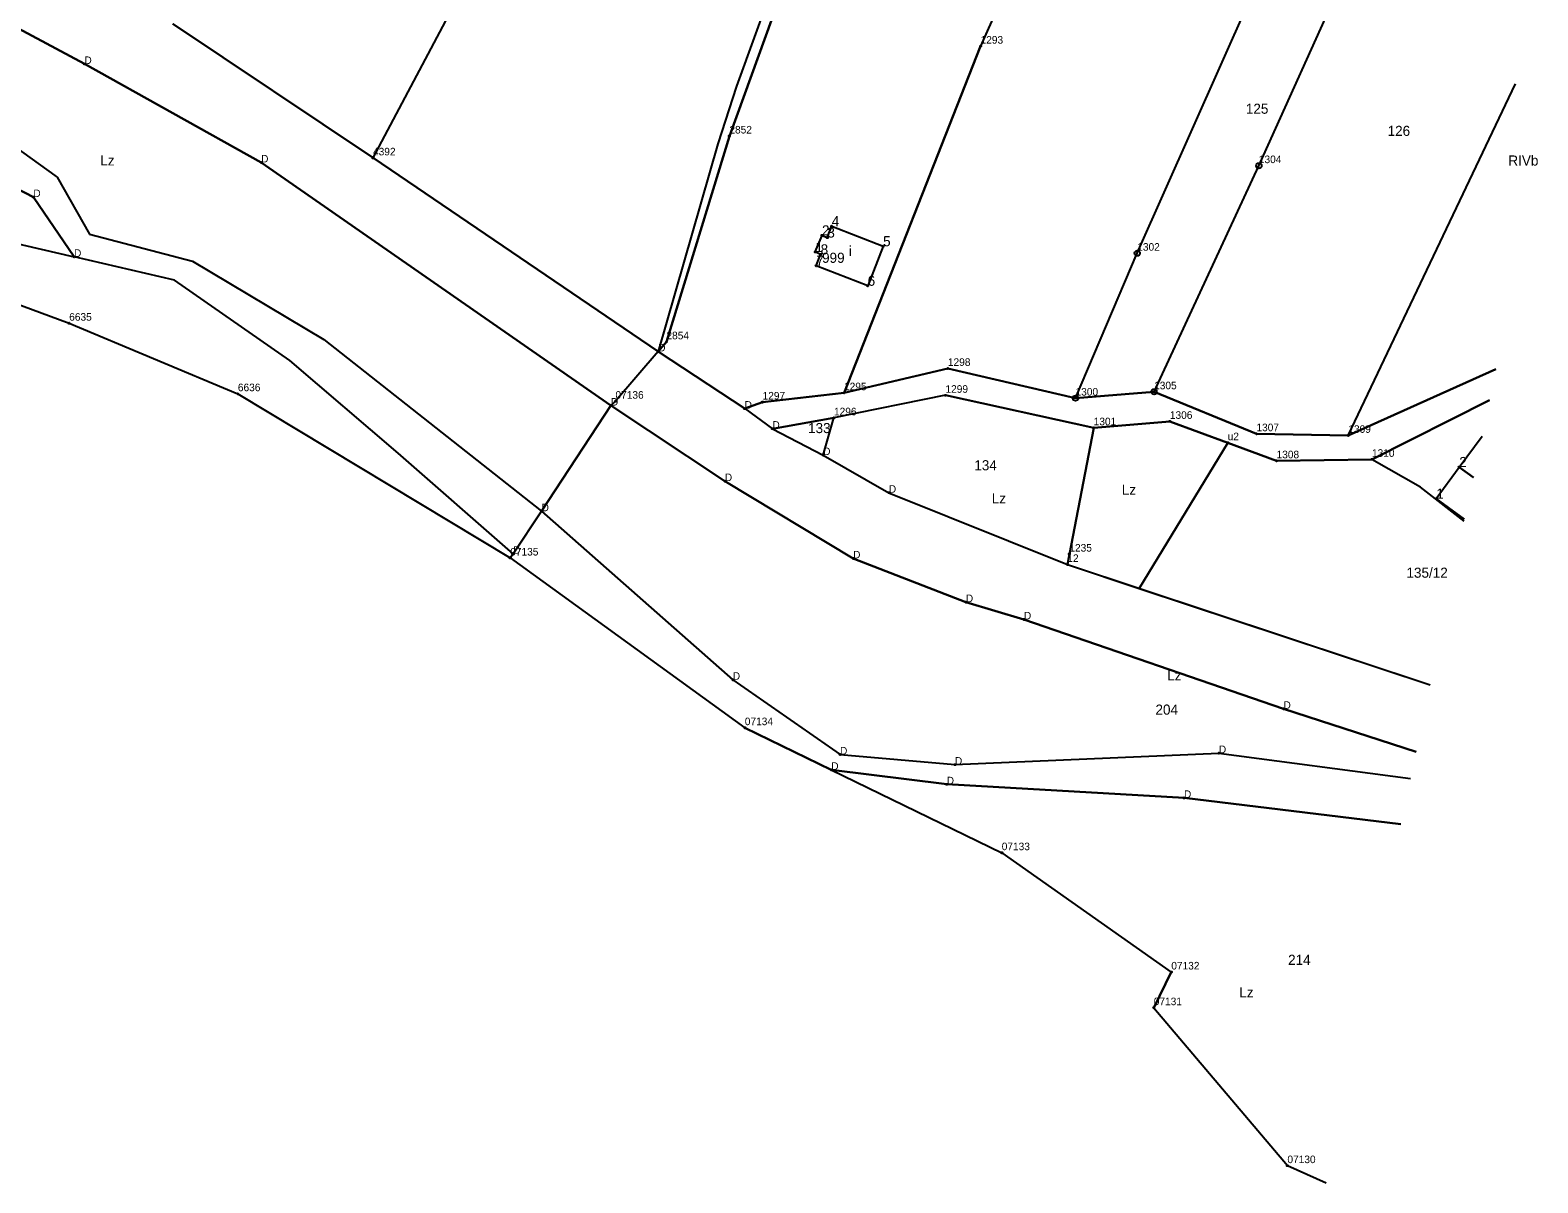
# Model space of a CAD drawing. Extents: x 7465393 to 7466459, y 5491258 to 5492404.
# Drawn here: x 7466235 to 7466458.9, y 5491258.3 to 5491429.5 of the extents above; entities that cross this region are included whole.
import ezdxf

# ---------------------------------------------------------------- set-up
doc = ezdxf.new("R2010")
doc.units = 0
for name, color, linetype in [('202-punkt graniczny', 7, 'Continuous'), ('202-punkt graniczny-Atr103', 7, 'Continuous'), ('203-punkt graniczny', 7, 'Continuous'), ('203-punkt graniczny-Atr103', 7, 'Continuous'), ('209-oznaczenie konturu klasyfikacyjnego', 7, 'Continuous'), ('210-oznaczenie konturu użytku gruntowego', 7, 'Continuous'), ('211-numer działki ewidencyjnej', 7, 'Continuous'), ('217-kontur klasyfikacyjny', 7, 'Continuous'), ('218-kontur użytku gruntowego', 7, 'Continuous'), ('219-działka ewidencyjna', 7, 'Continuous'), ('312-budynek ewidencyjny', 7, 'Continuous'), ('312-oznaczenie budynku ewidencyjnego', 7, 'Continuous'), ('312-oznaczenie budynku ewidencyjnego-Atr117', 7, 'Continuous'), ('Punkt budynku', 7, 'Continuous'), ('Punkt budynku-Atr104', 7, 'Continuous')]:
    doc.layers.add(name, color=color, linetype=linetype)

# ---------------------------------------------------------------- blocks, each defined once
blk = doc.blocks.new('203')
blk.add_circle((0, 0), 0.09)
blk = doc.blocks.new('202')
blk.add_circle((0, 0), 0.4)
blk = doc.blocks.new('PUNKTBUD')
blk.add_circle((0, 0), 0.09)

msp = doc.modelspace()

# ---------------------------------------------------------------- linework, layer by layer
at = {"layer": '217-kontur klasyfikacyjny'}
for points in [[(7466390.84, 5491460.24), (7466376.13, 5491427.07)], [(7466376.13, 5491427.07), (7466355.86, 5491375.61)], [(7466235.52, 5491404.67), (7466207.38, 5491419.24)], [(7466241.56, 5491395.8), (7466235.52, 5491404.67)], [(7466256.45, 5491392.36), (7466241.56, 5491395.8)], [(7466223.97, 5491392.21), (7466240.84, 5491385.94)], [(7466273.58, 5491380.42), (7466256.45, 5491392.36)], [(7466240.84, 5491385.94), (7466265.88, 5491375.47)], [(7466289.66, 5491366.65), (7466273.58, 5491380.42)], [(7466355.86, 5491375.61), (7466371.28, 5491379.23)], [(7466371.28, 5491379.23), (7466390.23, 5491374.82)], [(7466430.72, 5491369.29), (7466452.64, 5491379.14)], [(7466265.88, 5491375.47), (7466306.31, 5491351.09)], [(7466390.23, 5491374.82), (7466401.89, 5491375.77)], [(7466401.89, 5491375.77), (7466417.08, 5491369.53)], [(7466451.68, 5491374.54), (7466434.23, 5491365.73)], [(7466417.08, 5491369.53), (7466430.72, 5491369.29)], [(7466412.81, 5491368.2), (7466399.69, 5491346.58)], [(7466420.07, 5491365.52), (7466412.81, 5491368.2)], [(7466306.73, 5491351.71), (7466289.66, 5491366.65)], [(7466434.23, 5491365.73), (7466420.07, 5491365.52)], [(7466441.44, 5491361.59), (7466434.23, 5491365.73)], [(7466447.93, 5491356.58), (7466441.44, 5491361.59)], [(7466306.31, 5491351.09), (7466306.73, 5491351.71)], [(7466399.69, 5491346.58), (7466442.85, 5491332.26)]]:
    msp.add_lwpolyline(points, dxfattribs=at)
at = {"layer": '218-kontur użytku gruntowego'}
for points in [[(7466243.1, 5491424.43), (7466171.64, 5491462.69)], [(7466390.84, 5491460.24), (7466376.13, 5491427.07)], [(7466345.55, 5491436.73), (7466339.91, 5491421.15)], [(7466346.31, 5491434.42), (7466338.84, 5491413.73)], [(7466256.21, 5491430.41), (7466285.94, 5491410.48)], [(7466211.1, 5491427.7), (7466239.05, 5491407.62)], [(7466376.13, 5491427.07), (7466355.86, 5491375.61)], [(7466269.33, 5491409.81), (7466243.1, 5491424.43)], [(7466339.91, 5491421.15), (7466337.12, 5491412.56)], [(7466235.52, 5491404.67), (7466207.38, 5491419.24)], [(7466337.12, 5491412.56), (7466328.28, 5491381.76)], [(7466338.84, 5491413.73), (7466329.5, 5491383.18)], [(7466321.26, 5491373.72), (7466269.33, 5491409.81)], [(7466285.94, 5491410.48), (7466328.28, 5491381.76)], [(7466239.05, 5491407.62), (7466243.84, 5491399.17)], [(7466241.56, 5491395.8), (7466235.52, 5491404.67)], [(7466243.84, 5491399.17), (7466259.15, 5491395.15)], [(7466256.45, 5491392.36), (7466241.56, 5491395.8)], [(7466259.15, 5491395.15), (7466278.64, 5491383.51)], [(7466273.58, 5491380.42), (7466256.45, 5491392.36)], [(7466278.64, 5491383.51), (7466310.97, 5491358.02)], [(7466329.5, 5491383.18), (7466328.28, 5491381.76)], [(7466328.28, 5491381.76), (7466321.93, 5491374.36)], [(7466328.28, 5491381.76), (7466341.11, 5491373.26)], [(7466289.66, 5491366.65), (7466273.58, 5491380.42)], [(7466371.28, 5491379.23), (7466355.86, 5491375.61)], [(7466390.23, 5491374.82), (7466371.28, 5491379.23)], [(7466452.64, 5491379.14), (7466430.72, 5491369.29)], [(7466321.93, 5491374.36), (7466321.26, 5491373.72)], [(7466343.77, 5491374.24), (7466341.11, 5491373.26)], [(7466355.86, 5491375.61), (7466343.77, 5491374.24)], [(7466370.92, 5491375.24), (7466354.37, 5491371.89)], [(7466392.92, 5491370.42), (7466370.92, 5491375.24)], [(7466401.89, 5491375.77), (7466390.23, 5491374.82)], [(7466417.08, 5491369.53), (7466401.89, 5491375.77)], [(7466434.23, 5491365.73), (7466451.68, 5491374.54)], [(7466321.26, 5491373.72), (7466310.97, 5491358.02)], [(7466338.17, 5491362.5), (7466321.26, 5491373.72)], [(7466341.11, 5491373.26), (7466345.23, 5491370.29)], [(7466354.37, 5491371.89), (7466345.23, 5491370.29)], [(7466345.23, 5491370.29), (7466352.77, 5491366.37)], [(7466392.92, 5491370.42), (7466389.31, 5491351.67)], [(7466404.23, 5491371.37), (7466392.92, 5491370.42)], [(7466412.81, 5491368.2), (7466404.23, 5491371.37)], [(7466430.72, 5491369.29), (7466417.08, 5491369.53)], [(7466399.69, 5491346.58), (7466412.81, 5491368.2)], [(7466412.81, 5491368.2), (7466420.07, 5491365.52)], [(7466306.73, 5491351.71), (7466289.66, 5491366.65)], [(7466352.77, 5491366.37), (7466362.52, 5491360.78)], [(7466420.07, 5491365.52), (7466434.23, 5491365.73)], [(7466441.44, 5491361.59), (7466434.23, 5491365.73)], [(7466357.21, 5491351.03), (7466338.17, 5491362.5)], [(7466362.52, 5491360.78), (7466389.01, 5491350.12)], [(7466447.93, 5491356.58), (7466441.44, 5491361.59)], [(7466310.97, 5491358.02), (7466306.73, 5491351.71)], [(7466310.97, 5491358.02), (7466339.35, 5491333.01)], [(7466306.73, 5491351.71), (7466306.31, 5491351.09)], [(7466389.31, 5491351.67), (7466389.01, 5491350.12)], [(7466306.31, 5491351.09), (7466341.13, 5491325.89)], [(7466373.95, 5491344.54), (7466357.21, 5491351.03)], [(7466389.01, 5491350.12), (7466399.69, 5491346.58)], [(7466399.69, 5491346.58), (7466442.85, 5491332.26)], [(7466382.57, 5491341.97), (7466373.95, 5491344.54)], [(7466421.1, 5491328.7), (7466382.57, 5491341.97)], [(7466339.35, 5491333.01), (7466355.27, 5491321.92)], [(7466440.77, 5491322.3), (7466421.1, 5491328.7)], [(7466341.13, 5491325.89), (7466353.97, 5491319.64)], [(7466355.27, 5491321.92), (7466372.33, 5491320.41)], [(7466372.33, 5491320.41), (7466411.51, 5491322.12)], [(7466411.51, 5491322.12), (7466439.94, 5491318.33)], [(7466353.97, 5491319.64), (7466379.27, 5491307.33)], [(7466371.11, 5491317.49), (7466353.97, 5491319.64)], [(7466406.33, 5491315.47), (7466371.11, 5491317.49)], [(7466438.54, 5491311.59), (7466406.33, 5491315.47)], [(7466379.27, 5491307.33), (7466404.44, 5491289.62)], [(7466404.44, 5491289.62), (7466401.84, 5491284.32)], [(7466401.84, 5491284.32), (7466421.68, 5491260.88)], [(7466421.68, 5491260.88), (7466427.41, 5491258.33)]]:
    msp.add_lwpolyline(points, dxfattribs=at)
at = {"layer": '219-działka ewidencyjna'}
for points in [[(7466171.64, 5491462.69), (7466243.1, 5491424.43)], [(7466390.84, 5491460.24), (7466376.13, 5491427.07)], [(7466399.39, 5491396.33), (7466419.99, 5491442.77)], [(7466417.44, 5491409.33), (7466429.86, 5491436.86)], [(7466285.94, 5491410.48), (7466299.32, 5491435.73)], [(7466338.84, 5491413.73), (7466346.31, 5491434.42)], [(7466285.94, 5491410.48), (7466256.21, 5491430.41)], [(7466355.86, 5491375.61), (7466376.13, 5491427.07)], [(7466243.1, 5491424.43), (7466269.33, 5491409.81)], [(7466430.72, 5491369.29), (7466455.52, 5491421.49)], [(7466207.38, 5491419.24), (7466235.52, 5491404.67)], [(7466329.5, 5491383.18), (7466338.84, 5491413.73)], [(7466269.33, 5491409.81), (7466321.26, 5491373.72)], [(7466328.28, 5491381.76), (7466285.94, 5491410.48)], [(7466401.89, 5491375.77), (7466417.44, 5491409.33)], [(7466198.08, 5491405.9), (7466241.56, 5491395.8)], [(7466235.52, 5491404.67), (7466241.56, 5491395.8)], [(7466390.23, 5491374.82), (7466399.39, 5491396.33)], [(7466223.97, 5491392.21), (7466240.84, 5491385.94)], [(7466240.84, 5491385.94), (7466265.88, 5491375.47)], [(7466328.28, 5491381.76), (7466329.5, 5491383.18)], [(7466328.28, 5491381.76), (7466321.93, 5491374.36)], [(7466328.28, 5491381.76), (7466341.11, 5491373.26)], [(7466355.86, 5491375.61), (7466371.28, 5491379.23)], [(7466371.28, 5491379.23), (7466390.23, 5491374.82)], [(7466430.72, 5491369.29), (7466452.64, 5491379.14)], [(7466265.88, 5491375.47), (7466306.31, 5491351.09)], [(7466321.26, 5491373.72), (7466321.93, 5491374.36)], [(7466341.11, 5491373.26), (7466343.77, 5491374.24)], [(7466343.77, 5491374.24), (7466355.86, 5491375.61)], [(7466370.92, 5491375.24), (7466354.37, 5491371.89)], [(7466370.92, 5491375.24), (7466392.92, 5491370.42)], [(7466390.23, 5491374.82), (7466401.89, 5491375.77)], [(7466401.89, 5491375.77), (7466417.08, 5491369.53)], [(7466434.23, 5491365.73), (7466451.68, 5491374.54)], [(7466310.97, 5491358.02), (7466321.26, 5491373.72)], [(7466321.26, 5491373.72), (7466338.17, 5491362.5)], [(7466341.11, 5491373.26), (7466345.23, 5491370.29)], [(7466345.23, 5491370.29), (7466354.37, 5491371.89)], [(7466352.77, 5491366.37), (7466354.37, 5491371.89)], [(7466345.23, 5491370.29), (7466352.77, 5491366.37)], [(7466389.31, 5491351.67), (7466392.92, 5491370.42)], [(7466392.92, 5491370.42), (7466404.23, 5491371.37)], [(7466404.23, 5491371.37), (7466412.81, 5491368.2)], [(7466417.08, 5491369.53), (7466430.72, 5491369.29)], [(7466420.07, 5491365.52), (7466412.81, 5491368.2)], [(7466352.77, 5491366.37), (7466362.52, 5491360.78)], [(7466420.07, 5491365.52), (7466434.23, 5491365.73)], [(7466338.17, 5491362.5), (7466357.21, 5491351.03)], [(7466362.52, 5491360.78), (7466389.01, 5491350.12)], [(7466306.73, 5491351.71), (7466310.97, 5491358.02)], [(7466310.97, 5491358.02), (7466339.35, 5491333.01)], [(7466306.73, 5491351.71), (7466306.31, 5491351.09)], [(7466389.01, 5491350.12), (7466389.31, 5491351.67)], [(7466306.31, 5491351.09), (7466341.13, 5491325.89)], [(7466357.21, 5491351.03), (7466373.95, 5491344.54)], [(7466389.01, 5491350.12), (7466442.85, 5491332.26)], [(7466373.95, 5491344.54), (7466382.57, 5491341.97)], [(7466382.57, 5491341.97), (7466421.1, 5491328.7)], [(7466339.35, 5491333.01), (7466355.27, 5491321.92)], [(7466421.1, 5491328.7), (7466440.77, 5491322.3)], [(7466353.97, 5491319.64), (7466341.13, 5491325.89)], [(7466355.27, 5491321.92), (7466372.33, 5491320.41)], [(7466372.33, 5491320.41), (7466411.51, 5491322.12)], [(7466411.51, 5491322.12), (7466439.94, 5491318.33)], [(7466353.97, 5491319.64), (7466379.27, 5491307.33)], [(7466353.97, 5491319.64), (7466371.11, 5491317.49)], [(7466371.11, 5491317.49), (7466406.33, 5491315.47)], [(7466406.33, 5491315.47), (7466438.54, 5491311.59)], [(7466379.27, 5491307.33), (7466404.44, 5491289.62)], [(7466401.84, 5491284.32), (7466404.44, 5491289.62)], [(7466401.84, 5491284.32), (7466421.68, 5491260.88)], [(7466421.68, 5491260.88), (7466427.41, 5491258.33)]]:
    msp.add_lwpolyline(points, dxfattribs=at)
at = {"layer": '312-budynek ewidencyjny'}
for points in [[(7466351.6, 5491396.52), (7466352.59, 5491398.98)], [(7466352.59, 5491398.98), (7466353.38, 5491398.66)], [(7466353.38, 5491398.66), (7466354.03, 5491400.34)], [(7466354.03, 5491400.34), (7466361.66, 5491397.37)], [(7466352.39, 5491396.16), (7466351.6, 5491396.52)], [(7466351.73, 5491394.48), (7466352.39, 5491396.16)], [(7466361.66, 5491397.37), (7466359.37, 5491391.5)], [(7466359.37, 5491391.5), (7466351.73, 5491394.48)], [(7466447.19, 5491364.59), (7466450.57, 5491369.2)], [(7466443.78, 5491359.9), (7466447.19, 5491364.59)], [(7466447.19, 5491364.59), (7466449.29, 5491363.06)], [(7466449.29, 5491363.06), (7466447.19, 5491364.59)], [(7466447.99, 5491356.83), (7466443.78, 5491359.9)]]:
    msp.add_lwpolyline(points, dxfattribs=at)

# ---------------------------------------------------------------- block references
at = {"layer": '202-punkt graniczny'}
for p in [(7466417.44, 5491409.33), (7466399.39, 5491396.33), (7466401.89, 5491375.77), (7466390.23, 5491374.82)]:
    msp.add_blockref('202', p, dxfattribs=at)
at = {"layer": '203-punkt graniczny'}
for p in [(7466376.13, 5491427.07), (7466243.1, 5491424.43), (7466338.84, 5491413.73), (7466269.33, 5491409.81), (7466285.94, 5491410.48), (7466235.52, 5491404.67), (7466241.56, 5491395.8), (7466240.84, 5491385.94), (7466329.5, 5491383.18), (7466328.28, 5491381.76), (7466371.28, 5491379.23), (7466265.88, 5491375.47), (7466321.26, 5491373.72), (7466321.93, 5491374.36), (7466343.77, 5491374.24), (7466355.86, 5491375.61), (7466370.92, 5491375.24), (7466341.11, 5491373.26), (7466354.37, 5491371.89), (7466345.23, 5491370.29), (7466392.92, 5491370.42), (7466404.23, 5491371.37), (7466417.08, 5491369.53), (7466430.72, 5491369.29), (7466412.81, 5491368.2), (7466352.77, 5491366.37), (7466420.07, 5491365.52), (7466434.23, 5491365.73), (7466338.17, 5491362.5), (7466362.52, 5491360.78), (7466310.97, 5491358.02), (7466306.73, 5491351.71), (7466389.31, 5491351.67), (7466306.31, 5491351.09), (7466357.21, 5491351.03), (7466389.01, 5491350.12), (7466373.95, 5491344.54), (7466382.57, 5491341.97), (7466339.35, 5491333.01), (7466421.1, 5491328.7), (7466341.13, 5491325.89), (7466355.27, 5491321.92), (7466372.33, 5491320.41), (7466411.51, 5491322.12), (7466353.97, 5491319.64), (7466371.11, 5491317.49), (7466406.33, 5491315.47), (7466379.27, 5491307.33), (7466404.44, 5491289.62), (7466401.84, 5491284.32), (7466421.68, 5491260.88)]:
    msp.add_blockref('203', p, dxfattribs=at)
at = {"layer": 'Punkt budynku'}
for p in [(7466352.59, 5491398.98), (7466353.38, 5491398.66), (7466354.03, 5491400.34), (7466351.6, 5491396.52), (7466352.39, 5491396.16), (7466361.66, 5491397.37), (7466351.73, 5491394.48), (7466359.37, 5491391.5), (7466447.19, 5491364.59), (7466443.78, 5491359.9)]:
    msp.add_blockref('PUNKTBUD', p, dxfattribs=at)

# ---------------------------------------------------------------- texts
at = {"layer": '202-punkt graniczny-Atr103'}
for s, p in [('1304', (7466417.44, 5491409.71)), ('1302', (7466399.39, 5491396.71)), ('1300', (7466390.23, 5491375.2)), ('1305', (7466401.89, 5491376.14))]:
    msp.add_text(s, height=1.125, dxfattribs=at).set_placement(p)
at = {"layer": '203-punkt graniczny-Atr103'}
for s, height, p in [('1293', 1.125, (7466376.13, 5491427.45)), ('D', 1.12, (7466243.1, 5491424.43)), ('2852', 1.125, (7466338.84, 5491414.11)), ('4392', 1.125, (7466285.94, 5491410.86)), ('D', 1.12, (7466269.33, 5491409.81)), ('D', 1.12, (7466235.52, 5491404.67)), ('D', 1.12, (7466241.56, 5491395.8)), ('6635', 1.125, (7466240.84, 5491386.32)), ('D', 1.12, (7466328.28, 5491381.76)), ('2854', 1.125, (7466329.5, 5491383.56)), ('1298', 1.125, (7466371.28, 5491379.61)), ('6636', 1.125, (7466265.88, 5491375.85)), ('1295', 1.125, (7466355.86, 5491375.99)), ('1299', 1.125, (7466370.92, 5491375.62)), ('D', 1.12, (7466321.26, 5491373.72)), ('07136', 1.125, (7466321.93, 5491374.74)), ('D', 1.12, (7466341.11, 5491373.26)), ('1297', 1.125, (7466343.77, 5491374.62)), ('1296', 1.125, (7466354.37, 5491372.27)), ('1301', 1.125, (7466392.92, 5491370.79)), ('1306', 1.125, (7466404.23, 5491371.75)), ('D', 1.12, (7466345.23, 5491370.29)), ('u2', 1.125, (7466412.81, 5491368.58)), ('1307', 1.125, (7466417.08, 5491369.91)), ('1309', 1.125, (7466430.72, 5491369.67)), ('D', 1.12, (7466352.77, 5491366.37)), ('1308', 1.125, (7466420.07, 5491365.89)), ('1310', 1.125, (7466434.23, 5491366.11)), ('D', 1.12, (7466338.17, 5491362.5)), ('D', 1.12, (7466362.52, 5491360.78)), ('D', 1.12, (7466310.97, 5491358.02)), ('07135', 1.125, (7466306.31, 5491351.46)), ('D', 1.12, (7466306.73, 5491351.71)), ('D', 1.12, (7466357.21, 5491351.03)), ('12', 1.125, (7466389.01, 5491350.5)), ('1235', 1.125, (7466389.31, 5491352.04)), ('D', 1.12, (7466373.95, 5491344.54)), ('D', 1.12, (7466382.57, 5491341.97)), ('D', 1.12, (7466339.35, 5491333.01)), ('D', 1.12, (7466421.1, 5491328.7)), ('07134', 1.125, (7466341.13, 5491326.27)), ('D', 1.12, (7466355.27, 5491321.92)), ('D', 1.12, (7466411.51, 5491322.12)), ('D', 1.12, (7466353.97, 5491319.64)), ('D', 1.12, (7466372.33, 5491320.41)), ('D', 1.12, (7466371.11, 5491317.49)), ('D', 1.12, (7466406.33, 5491315.47)), ('07133', 1.125, (7466379.27, 5491307.71)), ('07132', 1.125, (7466404.44, 5491290)), ('07131', 1.125, (7466401.84, 5491284.7)), ('07130', 1.125, (7466421.68, 5491261.25))]:
    msp.add_text(s, height=height, dxfattribs=at).set_placement(p)
at = {"layer": '209-oznaczenie konturu klasyfikacyjnego'}
msp.add_text('RIVb', height=1.5, dxfattribs=at).set_placement((7466454.48, 5491409.35))
at = {"layer": '210-oznaczenie konturu użytku gruntowego'}
for p in [(7466245.45, 5491409.36), (7466377.79, 5491359.2), (7466397.09, 5491360.47), (7466403.83, 5491332.92), (7466414.53, 5491285.85)]:
    msp.add_text('Lz', height=1.5, dxfattribs=at).set_placement(p)
at = {"layer": '211-numer działki ewidencyjnej'}
for s, p in [('125', (7466415.51, 5491417.04)), ('126', (7466436.55, 5491413.75)), ('133', (7466350.52, 5491369.63)), ('134', (7466375.2, 5491364.11)), ('135/12', (7466439.35, 5491348.16)), ('204', (7466402.09, 5491327.83)), ('214', (7466421.78, 5491290.69))]:
    msp.add_text(s, height=1.5, dxfattribs=at).set_placement(p)
at = {"layer": '312-oznaczenie budynku ewidencyjnego'}
msp.add_text('999', height=1.5, dxfattribs=at).set_placement((7466352.6, 5491394.91))
at = {"layer": '312-oznaczenie budynku ewidencyjnego-Atr117'}
msp.add_text('i', height=1.5, dxfattribs=at).set_placement((7466356.57, 5491395.92))
at = {"layer": 'Punkt budynku-Atr104'}
for s, p in [('4', (7466354.03, 5491400.34)), ('2', (7466352.59, 5491398.98)), ('3', (7466353.38, 5491398.66)), ('5', (7466361.66, 5491397.37)), ('1', (7466351.6, 5491396.52)), ('8', (7466352.39, 5491396.16)), ('7', (7466351.73, 5491394.48)), ('6', (7466359.37, 5491391.5)), ('2', (7466447.19, 5491364.59)), ('1', (7466443.78, 5491359.9))]:
    msp.add_text(s, height=1.5, dxfattribs=at).set_placement(p)

doc.saveas('drawing.dxf')
